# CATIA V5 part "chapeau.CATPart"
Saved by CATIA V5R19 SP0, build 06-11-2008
Part number: Part3
Bounding box of the stored display mesh (mm): x -69.981 to 69.981, y 0 to 30, z -69.908 to 69.908
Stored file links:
  F:\20\chapeau.CATPart
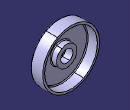
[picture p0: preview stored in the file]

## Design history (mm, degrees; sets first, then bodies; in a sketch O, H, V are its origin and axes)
Body1 (main body)
  Sketch1 on yz-plane, origin (0, 0, 0), H (0, 1, 0), V (0, 0, 1)
    point P1 (0, 15)
    line L1 (0, 15) -> (0, 70)
    line L2 (0, 70) -> (30, 70)
    line L3 (30, 70) -> (30, 65)
    line L4 (30, 65) -> (5, 65)
    line L5 (5, 65) -> (5, 25)
    line L6 (5, 25) -> (19.3719, 25)
    line L7 (19.3719, 25) -> (19.3719, 15)
    line L8 (19.3719, 15) -> (0, 15)
    length L1 = 55
    length L2 = 30
    length L3 = 5
    length L7 = 10
    distance L8 H = 15
    distance L5 L1 = 5
    coincidence: P1 V
    vertical: L1 V, L3 V, L5 V, L7 V
    horizontal: L2 H, L4 H, L6 H, L8 H
  Shaft1: profile Sketch1, axis Sketch1.H, angle 360
  Fillet1: radius 2, on face of Shaft1 from Sketch1.L5
  Fillet2: radius 2, on face of Shaft1 from Sketch1.L1
  Point1: type Center, Curve edge [face of Fillet2 | face of Shaft1 from Sketch1.L1]
  Line1: type Normal, RefSkin face of Shaft1 from Sketch1.L1, Start 0, End 20, RefPoint Point1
